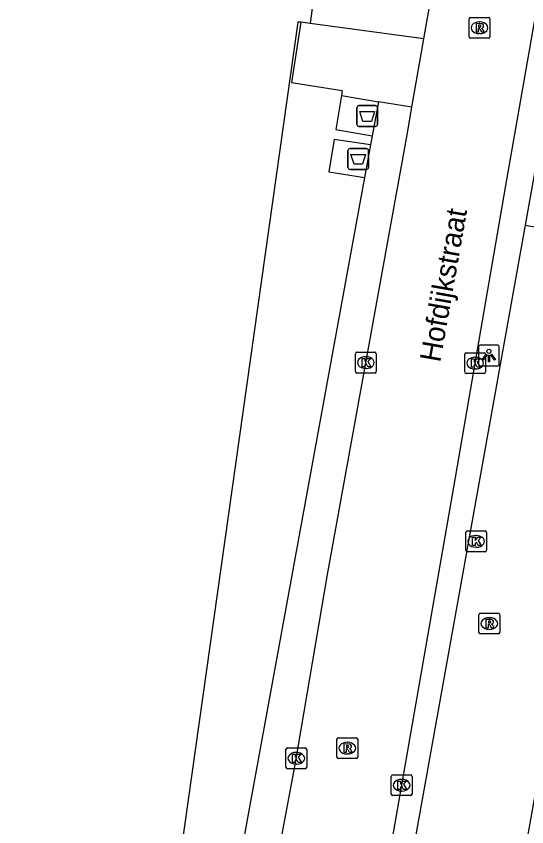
# Model space of a CAD drawing. Extents: x 161402 to 161933, y 381650 to 382313.
# Drawn here: x 161815.8 to 161840.28, y 382017.16 to 382056.07 of the extents above; entities that cross this region are included whole.
import ezdxf

# ---------------------------------------------------------------- set-up
doc = ezdxf.new("R2010")
doc.units = 0
for name, color, linetype in [('IMGEO_Afval_apart_plaats', 7, 'Continuous'), ('IMGEO_Groenvoorziening', 7, 'Continuous'), ('IMGEO_Kolk', 7, 'Continuous'), ('IMGEO_Lichtpunt', 7, 'Continuous'), ('IMGEO_Openbare_ruimte_label', 7, 'Continuous'), ('IMGEO_Parkeervlak_gesloten', 7, 'Continuous'), ('IMGEO_Rijbaan_lokaal_gesloten', 7, 'Continuous'), ('IMGEO_Rijbaan_lokaal_open', 7, 'Continuous'), ('IMGEO_Rioolput', 7, 'Continuous'), ('IMGEO_Voetpad_gesloten', 7, 'Continuous')]:
    doc.layers.add(name, color=color, linetype=linetype)

msp = doc.modelspace()

# ---------------------------------------------------------------- linework, layer by layer
at = {"layer": 'IMGEO_Afval_apart_plaats'}
for p, q in [((161832.234, 382051.78), (161833.024, 382051.78)), ((161833.024, 382051.78), (161832.234, 382051.78)), ((161832.134, 382050.88), (161832.134, 382051.68)), ((161832.134, 382051.68), (161832.134, 382050.88)), ((161833.124, 382051.68), (161833.124, 382050.88)), ((161833.124, 382050.88), (161833.124, 382051.68)), ((161833.024, 382050.78), (161832.234, 382050.78)), ((161832.234, 382050.78), (161833.024, 382050.78)), ((161831.705, 382048.818), (161831.705, 382049.618)), ((161831.705, 382049.618), (161831.705, 382048.818)), ((161831.805, 382049.718), (161832.595, 382049.718)), ((161832.595, 382049.718), (161831.805, 382049.718)), ((161832.695, 382049.618), (161832.695, 382048.818)), ((161832.695, 382048.818), (161832.695, 382049.618)), ((161832.595, 382048.718), (161831.805, 382048.718)), ((161831.805, 382048.718), (161832.595, 382048.718))]:
    msp.add_line(p, q, dxfattribs=at)
for points in [[(161832.277, 382051.494), (161832.981, 382051.494), (161832.832, 382051.024), (161832.426, 382051.024), (161832.277, 382051.494)], [(161831.848, 382049.432), (161832.552, 382049.432), (161832.403, 382048.962), (161831.997, 382048.962), (161831.848, 382049.432)]]:
    msp.add_lwpolyline(points, dxfattribs=at)
for centre, start, end in [((161832.234, 382051.68), 90, 180), ((161832.234, 382051.68), 90, 180), ((161833.024, 382051.68), 0, 90), ((161833.024, 382051.68), 360, 90), ((161832.234, 382050.88), 180, 270), ((161832.234, 382050.88), 180, 270), ((161833.024, 382050.88), 270, 0), ((161833.024, 382050.88), 270, 0), ((161831.805, 382049.618), 90, 180), ((161831.805, 382049.618), 90, 180), ((161832.595, 382049.618), 0, 90), ((161832.595, 382049.618), 360, 90), ((161831.805, 382048.818), 180, 270), ((161831.805, 382048.818), 180, 270), ((161832.595, 382048.818), 270, 0), ((161832.595, 382048.818), 270, 0)]:
    msp.add_arc(centre, 0.1, start, end, dxfattribs=at)
at = {"layer": 'IMGEO_Groenvoorziening'}
msp.add_lwpolyline([(161829.439, 382055.781), (161829.294, 382055.793), (161815.795, 381959.903)], dxfattribs=at)
at = {"layer": 'IMGEO_Kolk'}
for p, q in [((161832.064, 382039.018), (161832.064, 382039.87)), ((161832.139, 382039.944), (161832.991, 382039.944)), ((161832.552, 382039.724), (161832.577, 382039.724)), ((161833.065, 382039.87), (161833.065, 382039.018)), ((161837.308, 382038.993), (161837.308, 382039.845)), ((161837.383, 382039.919), (161838.235, 382039.919)), ((161837.796, 382039.699), (161837.821, 382039.699)), ((161838.309, 382039.845), (161838.309, 382038.993)), ((161832.991, 382038.944), (161832.139, 382038.944)), ((161832.575, 382039.164), (161832.55, 382039.164)), ((161838.235, 382038.919), (161837.383, 382038.919)), ((161837.819, 382039.139), (161837.794, 382039.139)), ((161837.357, 382030.436), (161837.357, 382031.288)), ((161837.432, 382031.362), (161838.284, 382031.362)), ((161837.845, 382031.142), (161837.87, 382031.142)), ((161838.358, 382031.288), (161838.358, 382030.436)), ((161838.284, 382030.362), (161837.432, 382030.362)), ((161837.868, 382030.582), (161837.843, 382030.582)), ((161828.729, 382020.023), (161828.729, 382020.875)), ((161828.804, 382020.949), (161829.656, 382020.949)), ((161829.217, 382020.729), (161829.242, 382020.729)), ((161829.73, 382020.875), (161829.73, 382020.023)), ((161829.656, 382019.949), (161828.804, 382019.949)), ((161829.24, 382020.169), (161829.215, 382020.169)), ((161833.782, 382018.73), (161833.782, 382019.582)), ((161833.857, 382019.656), (161834.709, 382019.656)), ((161834.27, 382019.436), (161834.295, 382019.436)), ((161834.783, 382019.582), (161834.783, 382018.73)), ((161834.709, 382018.656), (161833.857, 382018.656)), ((161834.293, 382018.876), (161834.268, 382018.876))]:
    msp.add_line(p, q, dxfattribs=at)
for points in [[(161832.064, 382039.018), (161832.064, 382039.87)], [(161832.139, 382039.944), (161832.991, 382039.944)], [(161832.385, 382039.644), (161832.508, 382039.644), (161832.508, 382039.493), (161832.638, 382039.644), (161832.802, 382039.644), (161832.656, 382039.493), (161832.809, 382039.244), (161832.657, 382039.244), (161832.572, 382039.408), (161832.508, 382039.341), (161832.508, 382039.244), (161832.385, 382039.244), (161832.385, 382039.644)], [(161833.065, 382039.87), (161833.065, 382039.018)], [(161837.308, 382038.993), (161837.308, 382039.845)], [(161837.383, 382039.919), (161838.235, 382039.919)], [(161838.309, 382039.845), (161838.309, 382038.993)], [(161837.629, 382039.619), (161837.752, 382039.619), (161837.752, 382039.468), (161837.882, 382039.619), (161838.046, 382039.619), (161837.9, 382039.468), (161838.053, 382039.219), (161837.901, 382039.219), (161837.816, 382039.383), (161837.752, 382039.316), (161837.752, 382039.219), (161837.629, 382039.219), (161837.629, 382039.619)], [(161832.991, 382038.944), (161832.139, 382038.944)], [(161838.235, 382038.919), (161837.383, 382038.919)], [(161837.357, 382030.436), (161837.357, 382031.288)], [(161837.432, 382031.362), (161838.284, 382031.362)], [(161838.358, 382031.288), (161838.358, 382030.436)], [(161837.678, 382031.062), (161837.801, 382031.062), (161837.801, 382030.911), (161837.931, 382031.062), (161838.095, 382031.062), (161837.949, 382030.911), (161838.102, 382030.662), (161837.95, 382030.662), (161837.865, 382030.826), (161837.801, 382030.759), (161837.801, 382030.662), (161837.678, 382030.662), (161837.678, 382031.062)], [(161838.284, 382030.362), (161837.432, 382030.362)], [(161828.729, 382020.023), (161828.729, 382020.875)], [(161828.804, 382020.949), (161829.656, 382020.949)], [(161829.05, 382020.649), (161829.173, 382020.649), (161829.173, 382020.498), (161829.303, 382020.649), (161829.467, 382020.649), (161829.321, 382020.498), (161829.474, 382020.249), (161829.322, 382020.249), (161829.237, 382020.413), (161829.173, 382020.346), (161829.173, 382020.249), (161829.05, 382020.249), (161829.05, 382020.649)], [(161829.73, 382020.875), (161829.73, 382020.023)], [(161829.656, 382019.949), (161828.804, 382019.949)], [(161833.782, 382018.73), (161833.782, 382019.582)], [(161833.857, 382019.656), (161834.709, 382019.656)], [(161834.783, 382019.582), (161834.783, 382018.73)], [(161834.103, 382019.356), (161834.226, 382019.356), (161834.226, 382019.205), (161834.356, 382019.356), (161834.52, 382019.356), (161834.374, 382019.205), (161834.527, 382018.956), (161834.375, 382018.956), (161834.29, 382019.12), (161834.226, 382019.053), (161834.226, 382018.956), (161834.103, 382018.956), (161834.103, 382019.356)], [(161834.709, 382018.656), (161833.857, 382018.656)]]:
    msp.add_lwpolyline(points, dxfattribs=at)
for centre, start, end in [((161832.141, 382039.868), 91.552, 178.448), ((161832.141, 382039.868), 91.552, 178.448), ((161832.989, 382039.868), 1.552, 88.448), ((161832.989, 382039.868), 1.552, 88.448), ((161837.385, 382039.843), 91.552, 178.448), ((161837.385, 382039.843), 91.552, 178.448), ((161838.233, 382039.843), 1.552, 88.448), ((161838.233, 382039.843), 1.552, 88.448), ((161832.141, 382039.02), 181.552, 268.448), ((161832.141, 382039.02), 181.552, 268.448), ((161832.989, 382039.02), 271.552, 358.448), ((161832.989, 382039.02), 271.552, 358.448), ((161837.385, 382038.995), 181.552, 268.448), ((161837.385, 382038.995), 181.552, 268.448), ((161838.233, 382038.995), 271.552, 358.448), ((161838.233, 382038.995), 271.552, 358.448), ((161837.434, 382031.286), 91.552, 178.448), ((161837.434, 382031.286), 91.552, 178.448), ((161838.282, 382031.286), 1.552, 88.448), ((161838.282, 382031.286), 1.552, 88.448), ((161837.434, 382030.438), 181.552, 268.448), ((161837.434, 382030.438), 181.552, 268.448), ((161838.282, 382030.438), 271.552, 358.448), ((161838.282, 382030.438), 271.552, 358.448), ((161828.806, 382020.873), 91.552, 178.448), ((161828.806, 382020.873), 91.552, 178.448), ((161829.654, 382020.873), 1.552, 88.448), ((161829.654, 382020.873), 1.552, 88.448), ((161828.806, 382020.025), 181.552, 268.448), ((161828.806, 382020.025), 181.552, 268.448), ((161829.654, 382020.025), 271.552, 358.448), ((161829.654, 382020.025), 271.552, 358.448), ((161833.859, 382019.58), 91.552, 178.448), ((161833.859, 382019.58), 91.552, 178.448), ((161834.707, 382019.58), 1.552, 88.448), ((161834.707, 382019.58), 1.552, 88.448), ((161833.859, 382018.732), 181.552, 268.448), ((161833.859, 382018.732), 181.552, 268.448), ((161834.707, 382018.732), 271.552, 358.448), ((161834.707, 382018.732), 271.552, 358.448)]:
    msp.add_arc(centre, 0.0765, start, end, dxfattribs=at)
for centre, major_axis, ratio, start_param, end_param in [((161832.551, 382039.444), (-0.387, 0.002), 0.722429, 4.712389, 7.853982), ((161832.576, 382039.444), (-0.39, 0.002), 0.717154, 1.570796, 4.712389), ((161837.795, 382039.419), (-0.387, 0.002), 0.722429, 4.712389, 7.853982), ((161837.82, 382039.419), (-0.39, 0.002), 0.717154, 1.570796, 4.712389), ((161837.844, 382030.862), (-0.387, 0.002), 0.722429, 4.712389, 7.853982), ((161837.869, 382030.862), (-0.39, 0.002), 0.717154, 1.570796, 4.712389), ((161829.216, 382020.449), (-0.387, 0.002), 0.722429, 4.712389, 7.853982), ((161829.241, 382020.449), (-0.39, 0.002), 0.717154, 1.570796, 4.712389), ((161834.269, 382019.156), (-0.387, 0.002), 0.722429, 4.712389, 7.853982), ((161834.294, 382019.156), (-0.39, 0.002), 0.717154, 1.570796, 4.712389)]:
    msp.add_ellipse(centre, major_axis=major_axis, ratio=ratio, start_param=start_param, end_param=end_param, dxfattribs=at)
at = {"layer": 'IMGEO_Lichtpunt'}
for p, q in [((161837.968, 382040.186), (161837.968, 382039.379)), ((161837.968, 382040.186), (161837.968, 382039.379)), ((161838.87, 382040.281), (161838.062, 382040.281)), ((161838.87, 382040.281), (161838.062, 382040.281)), ((161838.964, 382039.379), (161838.964, 382040.186)), ((161838.964, 382039.379), (161838.964, 382040.186)), ((161838.062, 382039.285), (161838.87, 382039.285)), ((161838.062, 382039.285), (161838.87, 382039.285))]:
    msp.add_line(p, q, dxfattribs=at)
for points in [[(161838.342, 382039.85), (161838.381, 382039.822), (161838.193, 382039.56), (161838.155, 382039.587), (161838.342, 382039.85)], [(161838.444, 382039.802), (161838.491, 382039.802), (161838.491, 382039.48), (161838.444, 382039.48), (161838.444, 382039.802)], [(161838.554, 382039.822), (161838.592, 382039.849), (161838.779, 382039.587), (161838.74, 382039.559), (161838.554, 382039.822)]]:
    msp.add_lwpolyline(points, dxfattribs=at)
msp.add_circle((161838.467, 382039.984), 0.0994, dxfattribs=at)
for centre, start, end in [((161838.062, 382040.186), 90, 180), ((161838.062, 382040.186), 90, 180), ((161838.87, 382040.186), 0, 90), ((161838.87, 382040.186), 0, 90), ((161838.062, 382039.379), 180, 270), ((161838.062, 382039.379), 180, 270), ((161838.87, 382039.379), 270, 0), ((161838.87, 382039.379), 270, 360)]:
    msp.add_arc(centre, 0.0946, start, end, dxfattribs=at)
at = {"layer": 'IMGEO_Parkeervlak_gesloten'}
msp.add_lwpolyline([(161836.652, 382071.701), (161832.064, 382072.53), (161829.897, 382055.72)], dxfattribs=at)
at = {"layer": 'IMGEO_Rijbaan_lokaal_gesloten'}
for points in [[(161841.73, 382054.571), (161840.202, 382046.042)], [(161840.202, 382046.042), (161845.388, 382045.117), (161836.518, 381995.382)]]:
    msp.add_lwpolyline(points, dxfattribs=at)
at = {"layer": 'IMGEO_Rijbaan_lokaal_open'}
for points in [[(161822.45, 381956.505), (161822.54, 381956.991), (161825.164, 381970.44), (161825.196, 381970.616), (161827.554, 381983.498), (161830.695, 382000), (161833.899, 382016.966), (161836.784, 382033.46), (161839.275, 382047.946), (161841.729, 382061.924), (161844.797, 382079.199), (161847.522, 382094.137), (161855.583, 382102.928), (161859.869, 382107.508)], [(161835.352, 382054.98), (161836.914, 382063.862), (161838.217, 382071.422)], [(161829.439, 382055.781), (161829.006, 382052.887), (161831.43, 382052.504), (161831.391, 382052.269)], [(161829.897, 382055.72), (161829.439, 382055.781)], [(161835.352, 382054.98), (161829.897, 382055.72)], [(161834.774, 382051.699), (161835.352, 382054.98)], [(161831.391, 382052.269), (161833.171, 382051.969)], [(161833.171, 382051.969), (161832.872, 382050.33)], [(161834.774, 382051.699), (161833.171, 382051.969)], [(161816.977, 381956.412), (161817.094, 381956.896), (161817.254, 381957.834), (161824.386, 381993.913), (161825.157, 381998.089), (161825.499, 382000), (161827.39, 382010.57), (161829.195, 382020.232), (161830.73, 382029.273), (161834.543, 382050.384), (161834.774, 382051.699)], [(161832.872, 382050.33), (161832.794, 382049.905)], [(161832.794, 382049.905), (161832.505, 382048.322)], [(161832.505, 382048.322), (161822.827, 381995.34), (161816.701, 381961.668), (161816.367, 381959.82)], [(161840.202, 382046.042), (161831.954, 382000), (161830.987, 381994.574)]]:
    msp.add_lwpolyline(points, dxfattribs=at)
at = {"layer": 'IMGEO_Rioolput'}
for p, q in [((161837.589, 382056.016), (161838.441, 382056.016)), ((161837.514, 382055.09), (161837.514, 382055.942)), ((161838.002, 382055.796), (161838.027, 382055.796)), ((161838.515, 382055.942), (161838.515, 382055.09)), ((161838.025, 382055.236), (161838, 382055.236)), ((161838.441, 382055.016), (161837.589, 382055.016)), ((161837.987, 382026.491), (161837.987, 382027.343)), ((161838.062, 382027.417), (161838.914, 382027.417)), ((161838.475, 382027.197), (161838.5, 382027.197)), ((161838.988, 382027.343), (161838.988, 382026.491)), ((161838.914, 382026.417), (161838.062, 382026.417)), ((161838.498, 382026.637), (161838.473, 382026.637)), ((161831.175, 382020.511), (161831.175, 382021.363)), ((161831.25, 382021.437), (161832.102, 382021.437)), ((161832.176, 382021.363), (161832.176, 382020.511)), ((161831.663, 382021.217), (161831.688, 382021.217)), ((161831.686, 382020.657), (161831.661, 382020.657)), ((161832.102, 382020.437), (161831.25, 382020.437))]:
    msp.add_line(p, q, dxfattribs=at)
for points in [[(161837.589, 382056.016), (161838.441, 382056.016)], [(161837.514, 382055.09), (161837.514, 382055.942)], [(161838.103, 382055.714), (161837.851, 382055.716), (161837.851, 382055.316)], [(161838.029, 382055.635), (161837.975, 382055.635), (161837.975, 382055.554)], [(161838.515, 382055.942), (161838.515, 382055.09)], [(161837.851, 382055.316), (161837.975, 382055.316), (161837.975, 382055.478), (161837.986, 382055.478)], [(161837.975, 382055.554), (161838.027, 382055.554)], [(161838.033, 382055.449), (161838.104, 382055.316), (161838.244, 382055.316), (161838.179, 382055.442)], [(161838.441, 382055.016), (161837.589, 382055.016)], [(161837.987, 382026.491), (161837.987, 382027.343)], [(161838.062, 382027.417), (161838.914, 382027.417)], [(161838.988, 382027.343), (161838.988, 382026.491)], [(161838.576, 382027.115), (161838.324, 382027.117), (161838.324, 382026.717)], [(161838.324, 382026.717), (161838.448, 382026.717), (161838.448, 382026.879), (161838.459, 382026.879)], [(161838.502, 382027.036), (161838.448, 382027.036), (161838.448, 382026.955)], [(161838.448, 382026.955), (161838.5, 382026.955)], [(161838.506, 382026.85), (161838.577, 382026.717), (161838.717, 382026.717), (161838.652, 382026.843)], [(161838.914, 382026.417), (161838.062, 382026.417)], [(161831.175, 382020.511), (161831.175, 382021.363)], [(161831.25, 382021.437), (161832.102, 382021.437)], [(161832.176, 382021.363), (161832.176, 382020.511)], [(161831.764, 382021.135), (161831.512, 382021.137), (161831.512, 382020.737)], [(161831.69, 382021.056), (161831.636, 382021.056), (161831.636, 382020.975)], [(161831.636, 382020.975), (161831.688, 382020.975)], [(161831.512, 382020.737), (161831.636, 382020.737), (161831.636, 382020.899), (161831.647, 382020.899)], [(161831.694, 382020.87), (161831.765, 382020.737), (161831.905, 382020.737), (161831.84, 382020.863)], [(161832.102, 382020.437), (161831.25, 382020.437)]]:
    msp.add_lwpolyline(points, dxfattribs=at)
for centre, radius, start, end in [((161837.591, 382055.94), 0.0765, 91.552, 178.448), ((161837.591, 382055.94), 0.0765, 91.552, 178.448), ((161838.439, 382055.94), 0.0765, 1.552, 88.448), ((161838.439, 382055.94), 0.0765, 1.552, 88.448), ((161838.035, 382055.539), 0.0964, 77.0061, 93.1865), ((161838.049, 382055.596), 0.0378, 276.6634, 79.6772), ((161838.102, 382055.604), 0.109, 350.3612, 89.416), ((161837.985, 382055.425), 0.0533, 26.0293, 88.6989), ((161838.011, 382055.743), 0.19, 274.7715, 282.9687), ((161838.1, 382055.604), 0.112, 277.5842, 350.9817), ((161838.084, 382055.389), 0.108, 29.5134, 73.7905), ((161837.591, 382055.092), 0.0765, 181.552, 268.448), ((161837.591, 382055.092), 0.0765, 181.552, 268.448), ((161838.439, 382055.092), 0.0765, 271.552, 358.448), ((161838.439, 382055.092), 0.0765, 271.552, 358.448), ((161838.064, 382027.341), 0.0765, 91.552, 178.448), ((161838.064, 382027.341), 0.0765, 91.552, 178.448), ((161838.912, 382027.341), 0.0765, 1.552, 88.448), ((161838.912, 382027.341), 0.0765, 1.552, 88.448), ((161838.458, 382026.826), 0.0533, 26.0293, 88.6989), ((161838.484, 382027.144), 0.19, 274.7715, 282.9687), ((161838.508, 382026.94), 0.0964, 77.0061, 93.1865), ((161838.522, 382026.997), 0.0378, 276.6634, 79.6772), ((161838.575, 382027.005), 0.109, 350.3612, 89.416), ((161838.573, 382027.005), 0.112, 277.5842, 350.9817), ((161838.557, 382026.79), 0.108, 29.5134, 73.7905), ((161838.064, 382026.493), 0.0765, 181.552, 268.448), ((161838.064, 382026.493), 0.0765, 181.552, 268.448), ((161838.912, 382026.493), 0.0765, 271.552, 358.448), ((161838.912, 382026.493), 0.0765, 271.552, 358.448), ((161831.252, 382021.361), 0.0765, 91.552, 178.448), ((161831.252, 382021.361), 0.0765, 91.552, 178.448), ((161832.1, 382021.361), 0.0765, 1.552, 88.448), ((161832.1, 382021.361), 0.0765, 1.552, 88.448), ((161831.672, 382021.164), 0.19, 274.7715, 282.9687), ((161831.696, 382020.96), 0.0964, 77.0061, 93.1865), ((161831.71, 382021.017), 0.0378, 276.6634, 79.6772), ((161831.763, 382021.025), 0.109, 350.3612, 89.416), ((161831.761, 382021.025), 0.112, 277.5842, 350.9817), ((161831.646, 382020.846), 0.0533, 26.0293, 88.6989), ((161831.745, 382020.81), 0.108, 29.5134, 73.7905), ((161831.252, 382020.513), 0.0765, 181.552, 268.448), ((161831.252, 382020.513), 0.0765, 181.552, 268.448), ((161832.1, 382020.513), 0.0765, 271.552, 358.448), ((161832.1, 382020.513), 0.0765, 271.552, 358.448)]:
    msp.add_arc(centre, radius, start, end, dxfattribs=at)
for centre, major_axis, ratio, start_param, end_param in [((161838.001, 382055.516), (-0.387, 0.002), 0.722429, 4.712389, 7.853982), ((161838.026, 382055.516), (-0.39, 0.002), 0.717154, 1.570796, 4.712389), ((161838.474, 382026.917), (-0.387, 0.002), 0.722429, 4.712389, 7.853982), ((161838.499, 382026.917), (-0.39, 0.002), 0.717154, 1.570796, 4.712389), ((161831.662, 382020.937), (-0.387, 0.002), 0.722429, 4.712389, 7.853982), ((161831.687, 382020.937), (-0.39, 0.002), 0.717154, 1.570796, 4.712389)]:
    msp.add_ellipse(centre, major_axis=major_axis, ratio=ratio, start_param=start_param, end_param=end_param, dxfattribs=at)
at = {"layer": 'IMGEO_Voetpad_gesloten'}
for points in [[(161831.391, 382052.269), (161831.118, 382050.626), (161832.872, 382050.33)], [(161832.794, 382049.905), (161831.04, 382050.152), (161830.782, 382048.597), (161832.505, 382048.322)]]:
    msp.add_lwpolyline(points, dxfattribs=at)

# ---------------------------------------------------------------- texts
at = {"layer": 'IMGEO_Openbare_ruimte_label'}
msp.add_text('Hofdijkstraat', height=1, rotation=79.9821, dxfattribs=at).set_placement((161836.13, 382039.423))

doc.saveas('drawing.dxf')
